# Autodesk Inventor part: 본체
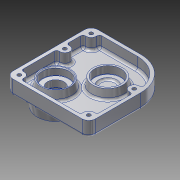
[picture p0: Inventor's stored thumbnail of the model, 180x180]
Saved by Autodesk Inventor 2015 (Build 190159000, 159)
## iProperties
Created: 2015-10
Part Number: 본체
Material: Aluminum 6061
Document SubType Name: Modeling
Designer: youjin20
Density: 2.7 g/cm^3
Appearance: Aluminum - Flat
Mass: 246.778 g
Surface Area: 390 cm^2
Volume: 91.3992 cm^3
Author: youjin20
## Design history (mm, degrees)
sketch "Sketch1"
  geometry: L1 (-22, 73)-(30, 73); L2 (70, 33)-(70, -22); L3 (62, -30)-(-22, -30); L4 (-30, -22)-(-30, 65); A1 r 8 centre (-22, 65) between (-22, 73) and (-30, 65); A2 r 8 centre (62, -22) between (62, -30) and (70, -22); A3 r 8 centre (-22, -22) between (-30, -22) and (-22, -30); A4 r 40 centre (30, 33) between (70, 33) and (30, 73); 4 further points
  constraints: 8 end point, 8 point on circle, 8 tangent, 6 point on line, 4 centre point, 2 equal radius, 2 parallel, 1 horizontal, 1 perpendicular
  dimensions: "d0" = 100 distance of point (70, -30) point (-30, -30); "d1" = 103 distance of point (-30, -30) point (-30, 73); "d2" = 30 distance from line of L3 point (0, 0); "d3" = 30 distance from line of L4 point (0, 0); "d4" = 8 radius of A1; "d5" = 40 radius of A4
extrude "Extrusion1" new body sketch "Sketch1" distance "d6" = 18; taper "d7" = 0 deg
shell "Shell1" dims "d8" = 4
sketch "Sketch2"
  geometry: C1 r 25 at (0, 0); 1 further point
  constraints: 1 centre point, 1 coincident
  dimensions: "d9" = 50 diameter of C1
extrude "Extrusion2" join sketch "Sketch2" distance "d10" = 15; taper "d11" = -10 deg
hole "Hole1" diameter "d14" = 24; stored, may be unused: countersink angle "d18" = 90 deg, drill point angle "d20" = 0 deg; dims "d15" = 6, "d16" = 28, "d17" = 11, "d19" = 13, "d21" = 10, "d22" = 10
sketch "Sketch3"
  geometry: C1 r 20 at (22, 26); 1 further point
  constraints: 1 centre point, 1 coincident
  dimensions: "d23" = 40 diameter of C1
extrude "Extrusion3" join sketch "Sketch3" distance "d24" = 11; taper "d25" = -10 deg
sketch "Sketch4"
  geometry: C1 r 10 at (0, 0); 1 further point
  constraints: 1 centre point, 1 coincident
  dimensions: "d26" = 20 diameter of C1
extrude "Extrusion4" cut sketch "Sketch4" distance "d27" = 8; taper "d28" = 0 deg
sketch "Sketch5"
  geometry: C1 r 16 at (0, 0); 1 further point
  constraints: 1 centre point, 1 coincident
  dimensions: "d29" = 32 diameter of C1
extrude "Extrusion5" cut sketch "Sketch5" distance "d30" = 11; taper "d31" = 0 deg
chamfer "Chamfer1" distance "d32" = 1; stored, may be unused: second distance "d33" = 2, angle "d34" = 45 deg
chamfer "Chamfer2" distance "d35" = 1; stored, may be unused: second distance "d36" = 2, angle "d37" = 45 deg
fillet "Fillet1" dims "d38" = 0.3
fillet "Fillet2" dims "d39" = 0.3
fillet "Fillet3" dims "d40" = 3
sketch "Sketch6"
  geometry: C1 r 20 at (52, 59); A1 r 40 centre (52, 59) between (92, 59) and (52, 99) reference; A2 r 36 centre (52, 59) between (88, 59) and (52, 95) reference; 1 further point
  constraints: 1 centre point, 1 coincident
  dimensions: "d44" = 40 diameter of C1
extrude "Extrusion6" join sketch "Sketch6" distance "d45" = 11; taper "d46" = -10 deg
hole "Hole2" diameter "d49" = 22; stored, may be unused: countersink angle "d53" = 90 deg, drill point angle "d55" = 0 deg; dims "d50" = 6, "d51" = 32, "d52" = 9, "d54" = 11, "d56" = 10, "d57" = 10
fillet "Fillet4" dims "d58" = 0.3
fillet "Fillet5" dims "d59" = 3
sketch "Sketch7"
  geometry: L1 (92, 4)-(92, 59) reference; L2 (0, -4)-(84, -4) reference; C1 r 6 at (0, 91); C2 r 6 at (0, 59); C3 r 6 at (0, 4); C4 r 6 at (84, 4); C5 r 6 at (84, 59); C6 r 8.172 at (52, 59) reference; 1 further point
  constraints: 5 centre point, 2 horizontal alignment, 2 vertical alignment
  dimensions: "d60" = 6 radius of C1; "d61" = 6 radius of C2; "d62" = 6 radius of C3; "d63" = 6 radius of C4; "d64" = 6 radius of C5; "d65" = 84 horizontal distance of C5.centre C1.centre; "d66" = 32 vertical distance of C6.centre C1.centre; "d67" = 55 distance of C4.centre C5.centre; "d68" = 8 distance from line of L1 C4.centre; "d69" = 8 distance from line of L1 C5.centre; "d70" = 8 distance from line of L2 C3.centre
extrude "Extrusion7" join sketch "Sketch7" distance "d71" = 14; taper "d72" = 0 deg
fillet "Fillet6" dims "d80" = 3
fillet "Fillet7" dims "d81" = 3
fillet "Fillet8" dims "d82" = 3
sketch "Sketch9"
  geometry: L1 (30, 65)-(30, -22) reference; L2 (22, -30)-(-62, -30) reference; L3 (-70, -22)-(-70, 33) reference; L4 (-30, 73)-(22, 73) reference; L5 (26, -13.056)-(26, 24.056) reference; L6 (26, 41.944)-(26, 56.056) reference; L7 (13.056, 69)-(-30, 69) reference; L8 (-66, 24.056)-(-66, -13.056) reference; L9 (-53.056, -26)-(13.056, -26) reference; A1 r 8 centre (22, -22) between (22, -30) and (30, -22) reference; A2 r 8 centre (-62, -22) between (-70, -22) and (-62, -30) reference; A3 r 40 centre (-30, 33) between (-30, 73) and (-70, 33) reference; A4 r 8 centre (22, 65) between (30, 65) and (22, 73) reference; A5 r 6 centre (22, -22) between (22.667, -16.037) and (16.037, -22.667) reference; A6 r 3 centre (23, -13.056) between (22.667, -16.037) and (26, -13.056) reference; A7 r 3 centre (23, 24.056) between (26, 24.056) and (22.667, 27.037) reference; A8 r 6 centre (22, 33) between (22.667, 38.963) and (22.667, 27.037) reference; A9 r 3 centre (23, 41.944) between (22.667, 38.963) and (26, 41.944) reference; A10 r 3 centre (23, 56.056) between (26, 56.056) and (22.667, 59.037) reference; A11 r 6 centre (22, 65) between (16.037, 65.667) and (22.667, 59.037) reference; A12 r 3 centre (13.056, 66) between (16.037, 65.667) and (13.056, 69) reference; A13 r 36 centre (-30, 33) between (-30, 69) and (-64.636, 42.814) reference; A14 r 3 centre (-61.75, 41.997) between (-64.636, 42.814) and (-61.833, 38.998) reference; A15 r 6 centre (-62, 33) between (-62.667, 27.037) and (-61.833, 38.998) reference; A16 r 3 centre (-63, 24.056) between (-62.667, 27.037) and (-66, 24.056) reference; A17 r 3 centre (-63, -13.056) between (-66, -13.056) and (-62.667, -16.037) reference; A18 r 6 centre (-62, -22) between (-56.037, -22.667) and (-62.667, -16.037) reference; A19 r 3 centre (-53.056, -23) between (-56.037, -22.667) and (-53.056, -26) reference; A20 r 3 centre (13.056, -23) between (13.056, -26) and (16.037, -22.667) reference; 6 further points
  constraints: 5 coincident
hole "Hole4" sketch "Sketch9" at (22, 65), (-62, 33), (-62, -22), (22, -22), (22, 33) diameter "d83" = 4.5; stored, may be unused: countersink angle "d87" = 90 deg, drill point angle "d89" = 0 deg; dims "d84" = 6, "d85" = 8, "d86" = 4.4, "d88" = 18
fillet "Fillet9" dims "d90" = 3
fillet "Fillet10" dims "d91" = 3
sketch "Sketch10"
  geometry: L1 (30, 5.311)-(30, 65) reference; L2 (22, 73)-(-30, 73) reference; 2 further points
  constraints: 1 other
  dimensions: "d92" = 40 distance from line of L1 point (-10, 53); "d93" = 20 distance from line of L2 point (-10, 53)
emboss "Emboss1" sketch "Sketch10" dims "d0" = 100, "d1" = 103, "d2" = 30, "d3" = 30, "d4" = 8, "d5" = 40, "d10" = 15, "d11" = -10 deg, "d94" = 0.5, "d95" = 0
sketch "Sketch11"
  geometry: A1 r 18 centre (0, 0) between (0, 18) and (18, 0); 3 further points
  constraints: 4 point on circle, 2 horizontal alignment, 2 vertical alignment, 1 centre point, 1 coincident
  dimensions: "d96" = 36 diameter of A1
hole "Hole5" sketch "Sketch11" at (0, 18), (18, 0), (-18, 0), (0, -18) diameter "d97" = 2.459; stored, may be unused: countersink angle "d101" = 90 deg, drill point angle "d103" = 118 deg; dims "d98" = 8, "d99" = 8, "d100" = 4.4, "d102" = 10
body "Solid1"
node "Projected Loop1"
node "Projected Loop3"
